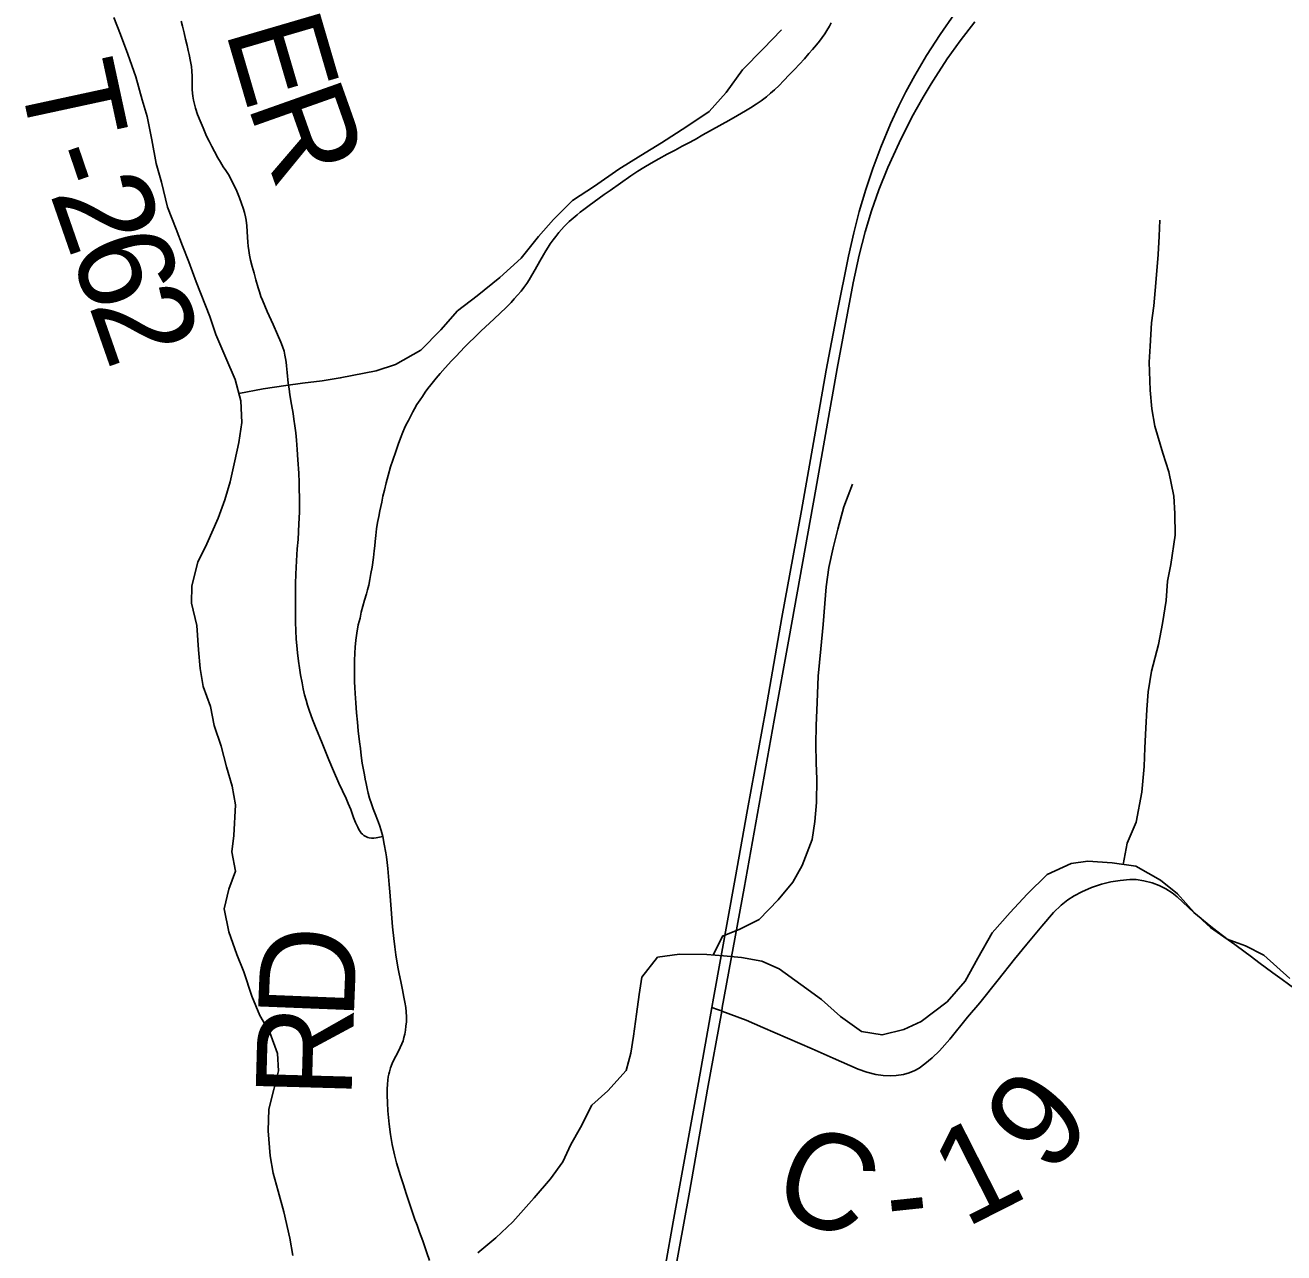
# Model space of a CAD drawing. Extents: x 1451455 to 1749751, y 218250 to 574981.
# Drawn here: x 1591899 to 1595834, y 282830 to 286670 of the extents above; entities that cross this region are included whole.
import ezdxf

# ---------------------------------------------------------------- set-up
doc = ezdxf.new("R2010")
doc.units = 0
for name, color, linetype in [('GM_X_County_Road', 7, 'Continuous'), ('GM_X_County_Road_Text', 7, 'Continuous'), ('GM_X_Minor_River', 7, 'Continuous'), ('GM_X_Township_Road', 7, 'Continuous'), ('GM_X_Township_Road_Text', 7, 'Continuous'), ('GM_X_US_Route', 7, 'Continuous')]:
    doc.layers.add(name, color=color, linetype=linetype)

msp = doc.modelspace()

# ---------------------------------------------------------------- linework, layer by layer
at = {"layer": 'GM_X_County_Road'}
for points in [[(1593016.5, 284132.1), (1593011.7, 284151.3), (1593006.5, 284167.3), (1593000, 284184.7), (1592993, 284202.5), (1592986.5, 284218.6), (1592980.9, 284234), (1592975.2, 284252), (1592971.3, 284267.4), (1592967.8, 284281.9), (1592964.4, 284298), (1592961.8, 284311), (1592959.2, 284324.5), (1592955.2, 284345.7), (1592952.7, 284361.8), (1592949.2, 284385.2), (1592946.6, 284407.4), (1592944, 284428.6), (1592940.1, 284462.1), (1592937.5, 284489.8), (1592934.8, 284518.5), (1592932.2, 284550.6), (1592930.1, 284579.7), (1592928.8, 284598.3), (1592928.3, 284616.1), (1592927.9, 284638.3), (1592927.9, 284661.3), (1592928.3, 284682.1), (1592929.2, 284705.1), (1592930.1, 284724.2), (1592932.2, 284746.3), (1592935.7, 284768.5), (1592940.1, 284794.1), (1592946.2, 284815.4), (1592949.2, 284833.6), (1592954.4, 284852.3), (1592960, 284870.9), (1592965.6, 284890.9), (1592969.1, 284903.5), (1592972.6, 284918.7), (1592976.1, 284935.6), (1592979.6, 284954.7), (1592983, 284974.6), (1592987.8, 285005), (1592990, 285025.4), (1592991.3, 285041.5), (1592992.6, 285054.9), (1592994.7, 285074), (1592996.9, 285094.4), (1593000.4, 285114.4), (1593003.9, 285132.6), (1593007.8, 285151.3), (1593013.4, 285178.2), (1593017.3, 285196.9), (1593021.6, 285215.5), (1593027.3, 285238.1), (1593033.4, 285261.1), (1593041.2, 285288.4), (1593048.1, 285309.7), (1593057.7, 285336.2), (1593065.1, 285357.9), (1593072.4, 285378.3), (1593079.8, 285396.9), (1593084.6, 285409.1), (1593090.2, 285421.2), (1593096.7, 285433.8), (1593102.8, 285446), (1593110.4, 285460), (1593115.8, 285469.9), (1593123.6, 285482.9), (1593133.2, 285497.6), (1593140.6, 285508.9), (1593148.8, 285521.5), (1593157.9, 285533.6), (1593166.6, 285544.9), (1593175.3, 285555.8), (1593183.5, 285565.7), (1593195.7, 285580.1), (1593211.5, 285598.1), (1593231.2, 285620), (1593244.7, 285633.9), (1593259.5, 285649.6), (1593272.1, 285662.6), (1593286.8, 285677.3), (1593303.3, 285693.4), (1593323.3, 285712.5), (1593365, 285751.5), (1593402.4, 285786.7), (1593417.5, 285802.3), (1593427.5, 285813.6), (1593438.3, 285825.3), (1593449.6, 285838.3), (1593457.4, 285849.2), (1593466.5, 285862.2), (1593473.9, 285873.9), (1593482.6, 285888.3), (1593492.6, 285905.6), (1593507.8, 285931.6), (1593519.5, 285951.2), (1593526.4, 285963.8), (1593533.4, 285975.1), (1593540.3, 285985.5), (1593549.4, 285998), (1593557.7, 286009.4), (1593567.4, 286021.7), (1593575.5, 286030.6), (1593584.1, 286040.2), (1593591.5, 286047.6), (1593599.3, 286055.4), (1593611.5, 286066.2), (1593624.1, 286077.1), (1593634.1, 286084.9), (1593644.9, 286093.3), (1593662.3, 286106.2), (1593708.7, 286139.9), (1593727.4, 286153.1), (1593759.4, 286176.2), (1593792.5, 286198.6), (1593813.9, 286212.9), (1593832.4, 286224.6), (1593856, 286238.6), (1593880.1, 286252.4), (1593906.2, 286266.3), (1593931, 286279.5), (1593952.2, 286291), (1593970.9, 286301), (1593993, 286312.7), (1594017.7, 286326.6), (1594098.9, 286371.8), (1594125.8, 286387.4), (1594151, 286402.2), (1594166.2, 286411.7), (1594184, 286423), (1594199.2, 286433.4), (1594216.1, 286446), (1594229.1, 286456.8), (1594241.7, 286468.1), (1594255.6, 286481.2), (1594269.9, 286495.9), (1594288.1, 286515.4), (1594303.3, 286531.1), (1594319.8, 286548), (1594334.6, 286564.9), (1594348.9, 286581), (1594360.6, 286594), (1594372.3, 286608.3), (1594381.9, 286620), (1594390.6, 286631.7), (1594398.4, 286642.6), (1594405.3, 286653.5), (1594413.1, 286667.3), (1594418.8, 286677.8)], [(1593162.4, 282806.2), (1593154.6, 282830), (1593148.5, 282848.3), (1593141.5, 282867.3), (1593131.6, 282894.3), (1593123.7, 282916), (1593116.8, 282934.2), (1593109.4, 282955.5), (1593099, 282987.1), (1593089.6, 283015.5), (1593081, 283042.8), (1593071.6, 283070.9), (1593059.4, 283111.1), (1593052.9, 283136.3), (1593045.8, 283168.6), (1593040.7, 283200.3), (1593036.4, 283231.9), (1593032.8, 283273.6), (1593031.4, 283298.8), (1593030, 283323.3), (1593030, 283342.2), (1593030.9, 283356.9), (1593032.1, 283369.5), (1593033.5, 283379.9), (1593035.2, 283388.6), (1593037.4, 283396.4), (1593040.7, 283408.8), (1593045.8, 283421.7), (1593050.4, 283431.2), (1593057.8, 283444.6), (1593065.2, 283458.5), (1593071.2, 283471.5), (1593076.4, 283483.7), (1593079.9, 283493.2), (1593082.9, 283503.6), (1593085.1, 283514.1), (1593087.3, 283526.2), (1593089, 283538.8), (1593090.3, 283552.3), (1593090.7, 283567.9), (1593089.9, 283583.1), (1593088.6, 283597.4), (1593086, 283613.4), (1593082.9, 283629.9), (1593078.2, 283652.9), (1593073, 283678.1), (1593067.7, 283702.4), (1593064.3, 283718.5), (1593061.2, 283735.8), (1593057.8, 283761.4), (1593054.3, 283786.6), (1593051.3, 283812.7), (1593047.3, 283849.1), (1593044.7, 283876.9), (1593042.6, 283904.7), (1593040.4, 283931.6), (1593038.3, 283958.9), (1593036.5, 283981.5), (1593034.8, 284007.1), (1593032.1, 284032.3), (1593030, 284050.9), (1593027.8, 284068.3), (1593026.1, 284080.9), (1593021.3, 284107.8), (1593016.5, 284132.1)], [(1595030.5, 283795.5), (1595076.8, 283852), (1595114, 283893.9), (1595137.6, 283917.1), (1595158.5, 283933.9), (1595178, 283946.7), (1595201.7, 283959.1), (1595232.2, 283972.1), (1595263.7, 283982.6), (1595292.7, 283989.9), (1595322.2, 283994.7), (1595352.1, 283997.3), (1595372.3, 283997.1), (1595395.6, 283993.7), (1595421.5, 283987), (1595443.5, 283978.9), (1595464.5, 283968.5), (1595484.5, 283956), (1595500.1, 283943.3), (1595552.7, 283894.2), (1595575.2, 283875.4), (1595582.6, 283869.1), (1595610.6, 283846.7), (1595659.7, 283808.9), (1595680.9, 283793.7), (1595712.4, 283770.1), (1595728.2, 283758.4), (1595759.8, 283735), (1595775.7, 283723.4), (1595799.4, 283706), (1595828.4, 283684.6), (1595867.9, 283655.7)], [(1594076.2, 283586), (1594152.7, 283557.3), (1594204.6, 283534.4), (1594359.1, 283467.8), (1594424.9, 283438.5), (1594502.7, 283404.3), (1594530.2, 283394.7), (1594558.4, 283387.9), (1594580.6, 283384.6), (1594603, 283383.5), (1594622.1, 283384.5), (1594644.2, 283388), (1594662.5, 283393.1), (1594680.2, 283400.1), (1594693.9, 283407.8), (1594711.8, 283420.8), (1594734.1, 283439.2), (1594757.3, 283461.8), (1594789.4, 283498.4), (1594844.8, 283567), (1594882.8, 283612.2), (1594940.4, 283683.7), (1594991.5, 283747.9), (1595030.5, 283795.5)], [(1594045.3, 283597.1), (1594062.9, 283590.8), (1594075.6, 283586.2), (1594076.2, 283586)]]:
    msp.add_lwpolyline(points, dxfattribs=at)
at = {"layer": 'GM_X_Minor_River'}
for points in [[(1592175.4, 286693.6), (1592196.7, 286641.3), (1592220, 286578.9), (1592245.1, 286508.5), (1592264.2, 286436.1), (1592279.6, 286383.8), (1592294.7, 286311.6), (1592307.7, 286237.3), (1592325, 286179), (1592344, 286100.7), (1592371.2, 286032.2), (1592390.6, 285979.9), (1592409.9, 285929.6), (1592433.2, 285867.2), (1592475.8, 285758.5), (1592495.2, 285702.1), (1592526.3, 285629.6), (1592555.4, 285561.2), (1592572.6, 285494.9), (1592575.8, 285426.7), (1592567, 285364.8), (1592554.2, 285306.9), (1592539.4, 285241), (1592522.7, 285185.2), (1592501.9, 285127.4), (1592466.9, 285047.8), (1592438.1, 284990.1), (1592419.2, 284916.3), (1592418.5, 284862.2), (1592435.6, 284791.9), (1592440.7, 284715.8), (1592445.9, 284657.6), (1592455.2, 284601.4), (1592478.5, 284539), (1592489.7, 284478.8)], [(1592566.7, 285517.6), (1592643.1, 285532), (1592713.3, 285543), (1592765.5, 285550.3), (1592827.6, 285557.5), (1592883.8, 285566.7), (1592996.2, 285589.2), (1593056.5, 285608.4), (1593135.1, 285653.4), (1593198, 285716.6), (1593250.7, 285776), (1593311.4, 285823.2), (1593382.2, 285880.3), (1593449, 285941.5), (1593503.9, 286008.8), (1593550.6, 286062.2), (1593609.4, 286121.5), (1593678.1, 286166.6), (1593754.8, 286219.6), (1593823.4, 286262.7), (1593887.9, 286301.9), (1593966.7, 286352.9), (1594037.3, 286400), (1594090.1, 286459.3), (1594141, 286530.7), (1594205.9, 286595.9), (1594262.7, 286655.2)], [(1595331.8, 284044.8), (1595343.6, 284111.5), (1595372.4, 284177.2), (1595389.6, 284271), (1595396.7, 284351), (1595399.4, 284409.1), (1595402.2, 284471.1), (1595404.9, 284529.1), (1595409.6, 284585.1), (1595420.4, 284649.1), (1595441.5, 284732.9), (1595454.4, 284798.8), (1595465.3, 284870.7), (1595470, 284930.8), (1595480.7, 284982.7), (1595493.9, 285074.6), (1595492.7, 285142.7), (1595489.4, 285196.8), (1595474.4, 285273.1), (1595455.1, 285331.4), (1595430.1, 285415.9), (1595420.8, 285470.1), (1595415.5, 285528.2), (1595412.6, 285616.3), (1595415.3, 285666.4), (1595420.2, 285738.4), (1595426.9, 285792.4), (1595433.8, 285864.4), (1595440.9, 285952.4), (1595443.6, 286010.4), (1595446.3, 286060.4)], [(1594049.8, 283761.2), (1594078.8, 283820.4), (1594133.1, 283841.7), (1594193.6, 283872.9), (1594252.4, 283934.1), (1594299.1, 283989.6), (1594327.8, 284041.2), (1594358.9, 284122.9), (1594367.6, 284178.9), (1594372.4, 284238.9), (1594373.3, 284310.9), (1594371.9, 284363), (1594370.7, 284421.1), (1594371.4, 284479.2), (1594374.3, 284551.2), (1594377.3, 284633.3), (1594386.4, 284719.2), (1594393.4, 284795.2), (1594398.2, 284861.2), (1594402.9, 284913.2), (1594411.6, 284973.2), (1594424.4, 285035.1), (1594439.2, 285093), (1594458.1, 285162.8), (1594485, 285234.5)], [(1592489.7, 284478.8), (1592510.9, 284414.5), (1592528.1, 284350.1), (1592545.4, 284289.8), (1592556.7, 284231.6), (1592551.5, 284135.6), (1592544.8, 284083.6), (1592556.1, 284023.4), (1592535.3, 283967.6), (1592520.5, 283905.7), (1592535.6, 283833.4), (1592560.8, 283763), (1592582.1, 283708.7), (1592607.2, 283632.2), (1592632.4, 283571.8), (1592663.8, 283519.3), (1592687, 283452.9), (1592690.3, 283398.8), (1592675.6, 283341), (1592660.8, 283279.1), (1592657.9, 283211), (1592664.9, 283132.9), (1592674.3, 283078.7), (1592689.6, 283022.4), (1592706.8, 282958.1), (1592725.7, 282875.7), (1592735.1, 282821.5)], [(1593313.7, 282829.6), (1593370.3, 282876.9), (1593423, 282926.3), (1593490, 283001.5), (1593540.8, 283060.8), (1593579.5, 283114.3), (1593604.2, 283168.1), (1593634.9, 283221.7), (1593669.8, 283291.3), (1593720.4, 283336.7), (1593777.3, 283400), (1593792, 283453.9), (1593800.6, 283507.8), (1593809.5, 283575.8), (1593818.3, 283637.7), (1593827, 283691.7), (1593875.8, 283755.1), (1593944, 283764.1), (1594030.1, 283763), (1594082, 283758.3), (1594138, 283753.5), (1594202, 283742.6), (1594255.7, 283717.8), (1594323.1, 283668.9), (1594388.6, 283621.9), (1594448, 283569), (1594513.4, 283522.1), (1594577.4, 283511.2), (1594645.6, 283528.3), (1594700, 283553.6), (1594780.8, 283614.5), (1594837.7, 283679.8), (1594876.6, 283751.4), (1594921.7, 283830.9), (1594978.5, 283894.2), (1595031.3, 283951.5), (1595094.1, 284012.8), (1595168.6, 284047.8), (1595220.8, 284055.1), (1595296.8, 284050), (1595370.7, 284039), (1595448.2, 283995.9), (1595501.7, 283953.1), (1595553, 283894.4), (1595604.5, 283847.6), (1595656.1, 283810.9), (1595713.9, 283790), (1595771.6, 283761.2), (1595852.7, 283688)]]:
    msp.add_lwpolyline(points, dxfattribs=at)
at = {"layer": 'GM_X_Township_Road'}
msp.add_lwpolyline([(1593016.5, 284132.1), (1592995.9, 284127.4), (1592989, 284126.5), (1592981.5, 284126.4), (1592974.5, 284127.5), (1592969.9, 284129.2), (1592963.8, 284131.7), (1592957.7, 284135.7), (1592953.4, 284139.1), (1592949, 284143), (1592945.6, 284147.8), (1592941.7, 284154.3), (1592938.2, 284161.3), (1592935.2, 284167.3), (1592931.7, 284176), (1592925.6, 284191.2), (1592916.5, 284216.4), (1592908.7, 284235), (1592902.2, 284251.1), (1592879.2, 284298.8), (1592862.7, 284337), (1592848.4, 284372.2), (1592826.7, 284423.8), (1592806.9, 284471.9), (1592796.7, 284498.1), (1592787.1, 284524), (1592781.1, 284542.8), (1592776.6, 284558.6), (1592772.4, 284575.7), (1592768.2, 284593.6), (1592764.2, 284613.1), (1592759.8, 284638.2), (1592756.4, 284659.5), (1592753.3, 284680.3), (1592749.7, 284706.9), (1592747.7, 284729.8), (1592745.9, 284749.4), (1592744.6, 284776.3), (1592743.7, 284801.8), (1592743.3, 284836.6), (1592743.5, 284867.4), (1592743.3, 284896.1), (1592744.1, 284923.2), (1592744.9, 284952.5), (1592745.5, 284973.3), (1592746.5, 284994.3), (1592749, 285031.5), (1592751.6, 285060.6), (1592754.6, 285110), (1592756.4, 285146.5), (1592756.3, 285170.3), (1592755.9, 285193.8), (1592755.5, 285217.2), (1592754.9, 285239.1), (1592753.7, 285268.9), (1592751.4, 285310.2), (1592749.5, 285342.8), (1592747.2, 285371.8), (1592745.1, 285395.2), (1592742, 285416.5), (1592739, 285437.7), (1592736, 285455.1), (1592731.2, 285482.9), (1592726.4, 285513.7), (1592723.8, 285532.3), (1592721.2, 285550.2), (1592717.7, 285583.1), (1592715.5, 285604.4), (1592714.2, 285615.7), (1592712.5, 285627), (1592710.8, 285638.2), (1592707.9, 285650.5), (1592702.9, 285664.7), (1592697.8, 285678.3), (1592687.8, 285702.2), (1592673.5, 285734.1), (1592655.2, 285774.8), (1592647.4, 285792.3), (1592640.2, 285809.9), (1592635.6, 285821.7), (1592630.9, 285835.7), (1592627, 285848.7), (1592620.1, 285873.5), (1592614.2, 285894.6), (1592608.3, 285915.6), (1592603.6, 285935.4), (1592600.1, 285950.7), (1592597.5, 285965.5), (1592596, 285978.6), (1592595, 285991.4), (1592594, 286006.7), (1592592.7, 286024.1), (1592591.4, 286042.8), (1592589.4, 286060.3), (1592587.5, 286070.7), (1592584.5, 286083.6), (1592580.3, 286097.6), (1592574.9, 286111.8), (1592568.3, 286129.8), (1592560.4, 286150.3), (1592552.8, 286166.9), (1592545, 286182.5), (1592536, 286199.4), (1592525.5, 286215.9), (1592518.1, 286227.2), (1592509.8, 286241.1), (1592501.1, 286255.4), (1592490.3, 286275), (1592482.1, 286290.6), (1592473.7, 286307), (1592466, 286323.1), (1592454.9, 286349), (1592445.6, 286370.5), (1592437.8, 286390.9), (1592431.5, 286410.2), (1592427.8, 286423), (1592424.7, 286435.5), (1592422.6, 286448.4), (1592421.1, 286468), (1592420.9, 286484.2), (1592421, 286496.3), (1592420.4, 286510.6), (1592419.6, 286526.3), (1592418.2, 286540.2), (1592415.9, 286555.9), (1592411.5, 286578), (1592408.7, 286590.5), (1592404.6, 286606.4), (1592400, 286625.7), (1592395.2, 286646.5), (1592390.4, 286666.6), (1592386.4, 286682.4)], dxfattribs=at)
at = {"layer": 'GM_X_US_Route'}
for points in [[(1593876.3, 282656), (1593924.4, 282927), (1594003.5, 283362.2), (1594045.3, 283597.1), (1594050.6, 283626.8), (1594118.5, 284000.7), (1594156.8, 284216.9), (1594213.7, 284529.5), (1594264.5, 284816.8), (1594325.6, 285152), (1594369.2, 285400.5), (1594402.8, 285590.8), (1594437.4, 285771), (1594473, 285947.5), (1594489.5, 286020.9), (1594506.5, 286087.4), (1594526.7, 286156.4), (1594548.5, 286221.4), (1594573.8, 286288.8), (1594603.8, 286361.2), (1594629.7, 286417.6), (1594651.8, 286461.4), (1594680.1, 286512.9), (1594717, 286574.7), (1594759.5, 286640.8), (1594804, 286705.4)], [(1594731, 286486.5), (1594745.2, 286509.6), (1594781.5, 286564.4), (1594821.7, 286620.5), (1594867.9, 286680.3)], [(1593895.3, 282581), (1593975.2, 283019.4), (1594032.2, 283342.1), (1594076.2, 283586), (1594078.1, 283596.8), (1594146.4, 283970.7), (1594240.2, 284496.4), (1594287.1, 284754.3), (1594370.3, 285218.7), (1594437.7, 285596.1), (1594487.6, 285863.6), (1594506, 285950.3), (1594524.4, 286023.5), (1594544.3, 286089.7), (1594567.3, 286154.8), (1594595.8, 286224.8), (1594631.2, 286302.4), (1594670.8, 286381.8), (1594705.7, 286445.1), (1594731, 286486.5)]]:
    msp.add_lwpolyline(points, dxfattribs=at)

# ---------------------------------------------------------------- texts
at = {"layer": 'GM_X_County_Road_Text'}
for s, rotation, p in [('D', 87.7153, (1592925.6, 283555.7)), ('R', 88.3918, (1592918.7, 283310.4)), ('9', 48.8971, (1595101.2, 283066.4)), ('C', 339.19, (1594220.3, 282966.5)), ('1', 26.8876, (1594837.7, 282906)), ('-', 6.0436, (1594601.5, 282859.4))]:
    msp.add_text(s, height=300, rotation=rotation, dxfattribs=at).set_placement(p)
at = {"layer": 'GM_X_Township_Road_Text'}
for s, rotation, p in [('E', 286.3289, (1592523.2, 286654)), ('T', 282.2076, (1591876.7, 286518.6)), ('R', 289.5084, (1592591.9, 286421.4)), ('-', 288.7783, (1591934.2, 286263.1)), ('2', 289.1791, (1591974.6, 286144.3)), ('6', 289.2326, (1592035.4, 285969.5)), ('2', 289.2541, (1592096.3, 285794.9))]:
    msp.add_text(s, height=300, rotation=rotation, dxfattribs=at).set_placement(p)

doc.saveas('drawing.dxf')
